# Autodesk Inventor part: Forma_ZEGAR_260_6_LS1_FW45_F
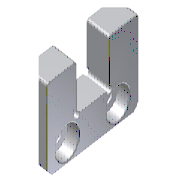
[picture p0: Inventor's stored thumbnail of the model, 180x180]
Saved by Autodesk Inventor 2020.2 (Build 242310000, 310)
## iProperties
Manager: www.cadconsulting.pl
Company: Fabian Stasiak CAD Consulting
Created: 2014-02
Part Number: Forma_ZEGAR_260_6_LS1_FW45_F
Material: 1.7131
Description: Straight interlocks
Document SubType Name: Modeling
Designer: F.Stasiak
Standard Revision: 1
Manufacturer: DME
Language: pl-PL
Size Designation: 50
Categories: <MemberInstance><Categories><Category DisplayName="Forma wtryskowa" InternalName="349578f2-f4d4-4954-8c09-8e99297a61c0" Mnemonic="MOLD"><Category DisplayName="E
Density: 7.85 g/cm^3
Appearance: Domyślna
Catalog Web Link: www.expertbooks.pl
IsCustomPart: 1
Author: F.Stasiak
Subject: Zbiór ćwiczeń. Autodesk Inventor 2020. Kurs Professional
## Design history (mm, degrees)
sketch "Sketch1"
  geometry: L1 (-25, 0)-(-10, 0); L2 (-10, 0)-(-10, -18); L3 (-9, -19)-(9, -19); L4 (10, -18)-(10, 0); L5 (10, 0)-(25, 0); L6 (25, 0)-(25, -36); L7 (25, -36)-(-25, -36); L8 (-25, -36)-(-25, 0); L9 (0, 5.4)-(0, -32.4) reference; L10 (-28, 0)-(28, 0) reference; A1 r 1 centre (-10, -19) between (-10, -18) and (-9, -19); A2 r 1 centre (10, -19) between (9, -19) and (10, -18); 1 further point
  constraints: 16 end point, 5 parallel, 4 point on circle, 4 point on line, 3 collinear, 2 centre point, 1 horizontal, 1 perpendicular, 2 other
  dimensions: "d0" = 50 distance between parallel lines of L6 L8 (= b); "d1" = 36 distance between parallel lines of L7 L1 (= s2); "d2" = 17 distance between parallel lines of L7 L3 (= s1); "d3" = 20 distance between parallel lines of L2 L4 (= b1); "d28" = 2 diameter of A1 (= R3); "d29" = 2 diameter of A2 (= R3)
extrude "Extrusion1" new body sketch "Sketch1" distance "d4" = 12.5 (= h_); taper "d5" = 0 deg
sketch "Sketch2"
  geometry: L1 (-7.2, 0)-(43.2, 0) reference; L2 (36, 25)-(36, -25) reference; 3 further points
  constraints: 1 symmetric about line, 1 vertical alignment
  dimensions: "d6" = 32 distance of point (27.5, -16) point (27.5, 16) (= b2); "d7" = 8.5 distance from line of L2 point (27.5, 16) (= a)
hole "Hole1" sketch "Sketch2" diameter "d8" = 6.6 (= D2); stored, may be unused: countersink angle "d12" = 90 deg, drill point angle "d14" = 0 deg; dims "d9" = 6, "d10" = 11 (= D1), "d11" = 6 (= M), "d13" = 12.5 (= h_)
hole "Hole2" sketch "Sketch2" diameter "d15" = 6.6 (= D2); stored, may be unused: countersink angle "d19" = 90 deg, drill point angle "d21" = 0 deg; dims "d16" = 6, "d17" = 11 (= D1), "d18" = 6 (= M), "d20" = 12.5 (= h_)
chamfer "Chamfer1" distance "d22" = 3 (= f1); stored, may be unused: second distance "d23" = 2, angle "d24" = 45 deg
chamfer "Chamfer2" distance "d25" = 6.5 (= f_); stored, may be unused: second distance "d26" = 2, angle "d27" = 45 deg
fillet "Fillet1" dims "d30" = 1 (= R1)
fillet "Fillet2" dims "d31" = 0.5 (= C1)
sketch "Sketch3"
  geometry: L1 (-1, 25)-(-33, 25) reference; L2 (-36, 19)-(-36, -19) reference; L3 (-33, -25)-(-1, -25) reference; L4 (0, 11)-(0, 19) reference; L5 (-36, 25)-(0, 25); L6 (0, 25)-(0, -25); L7 (0, -25)-(-36, -25); L8 (-36, -25)-(-36, 25); 1 further point
  constraints: 8 end point, 4 collinear, 2 parallel, 1 horizontal, 1 perpendicular
extrude_surface "ExtrusionSrf1" sketch "Sketch3" dims "d32" = 25 (= 2 x h_), "d33" = 0
fillet "Fillet3" dims "d34" = 2 (= R3)
feature "Stitch Surface1" dims "d41" = 0.254 (derived)
body "Solid1"
body "Srf1"
body "Srf2"
body "Srf3"
body "Srf4"
patch "Boundary Patch1" dims "d35" = 0, "d36" = 0, "d37" = 0
patch "Boundary Patch2" dims "d38" = 0, "d39" = 0, "d40" = 0
other parameters: "b" = 50 [user parameter; used in 1 equation term], "a" = 8.5 [user parameter; used in 1 equation term], "b1" = 20 [user parameter; used in 1 equation term], "b2" = 32 [user parameter; used in 1 equation term], "f_" = 6.5 [user parameter; used in 1 equation term], "f1" = 3 [user parameter; used in 1 equation term], "h_" = 12.5 [user parameter; used in 4 equation terms], "s1" = 17 [user parameter; used in 1 equation term], "s2" = 36 [user parameter; used in 1 equation term], "D1" = 11 [user parameter; used in 2 equation terms], "D2" = 6.6 [user parameter; used in 2 equation terms], "M" = 6 [user parameter; used in 2 equation terms], "C1" = 0.5 [user parameter; used in 1 equation term], "R1" = 1 [user parameter; used in 1 equation term], "R3" = 2 [user parameter; used in 3 equation terms]
